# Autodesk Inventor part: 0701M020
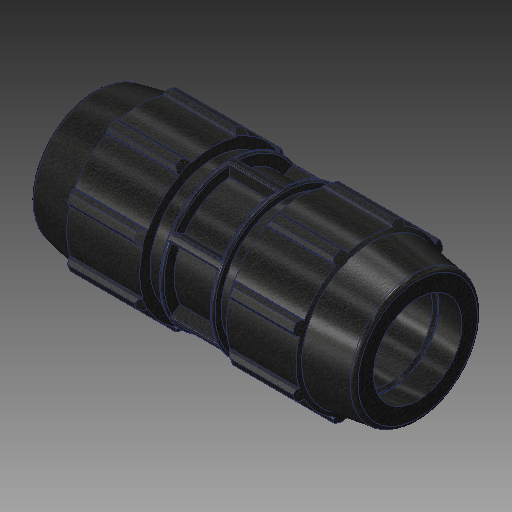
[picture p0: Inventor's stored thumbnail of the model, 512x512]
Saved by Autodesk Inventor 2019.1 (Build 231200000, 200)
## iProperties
Created: 2017-02
Part Number: 0701M020
Material: PVC-Piping
Description: PLASSON COUPLER 2'' - 63mm
Document SubType Name: Modeling
Designer: KIM
Mass: 92.6774 g
Surface Area: 199.44 cm^2
Volume: 66.1981 cm^3
Density: 1.4 g/cm^3
Appearance: PTFE
Author: KIM
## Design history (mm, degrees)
derived "0701M.ipt"
feature "Solid1::0701M.ipt"
tag "TaggingFeature1"
body "Solid1"
other parameters: "d2" = 63, "d4" = 19.15583, "d5" = 32.83857, "d7" = 113.03, "d8" = 84.7725, "d9" = 32.83857, "d11" = 3.28386, "d12" = 90.424, "d13" = 120 deg, "d14" = 90.15, "d15" = 8 deg, "d16" = 101.727, "d18" = 3.005, "d19" = 35 deg, "d20" = 17.5 deg, "d21" = 105.1179, "d23" = 0, "d25" = 360 deg, "d27" = 2.2606, "d33" = 1.202, "d34" = 5.6515, "d36" = 0, "d37" = 1.202, "d38" = 1.202, "d40" = 360 deg, "d42" = 50.5714, "d43" = 3.3909, "d46" = 1.803, "d50" = 48.08, "d51" = 112.014, "d53" = 3.28386, "d54" = 50.5714, "d55" = 120 deg, "d56" = 12 deg, "d57" = 19.15583, "d58" = 229.87, "d59" = 32.83857, "d63" = 32.83857, "d68" = 0, "d69" = 1.202, "d70" = 3.005, "d72" = 0, "d73" = 3.3909, "d77" = 112.014, "d78" = 60.1, "d_" = 60.1, "E_" = 113.03, "H_" = 229.87, "l_" = 112.014, "d_1" = 63
